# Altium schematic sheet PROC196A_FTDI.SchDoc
size 431 x 279 mm; Date: Not shown in title block; ApprovedBy: Not shown in title block; CheckedBy: Not shown in title block; Author: Not shown in title block; CompanyName: Not shown in title block; Engineer: Not shown in title block; Organization: Not shown in title block; Address1: Not shown in title block; Address2: Not shown in title block; Address3: Not shown in title block; Address4: Not shown in title block; DocumentNumber: 17; Revision: Use project parameter SCH_Rev; SheetNumber: 17; SheetTotal: 25; PageSetup: Record=PageOptions¦CenterHorizontal=True¦CenterVertical=True¦PrintScale=1.00¦XCorrection=1.00¦YCorrection=1.00¦PrintKind=0¦BorderSize=5000000¦LeftOffset=0¦BottomOffset=0¦Orientation=2¦PaperLength=1000¦PaperWidth=1000¦Scale=100¦PaperSource=15¦PrintQuality=600¦MediaType=1¦DitherType=10¦PaperKind=Letter¦PrintScaleMode=1
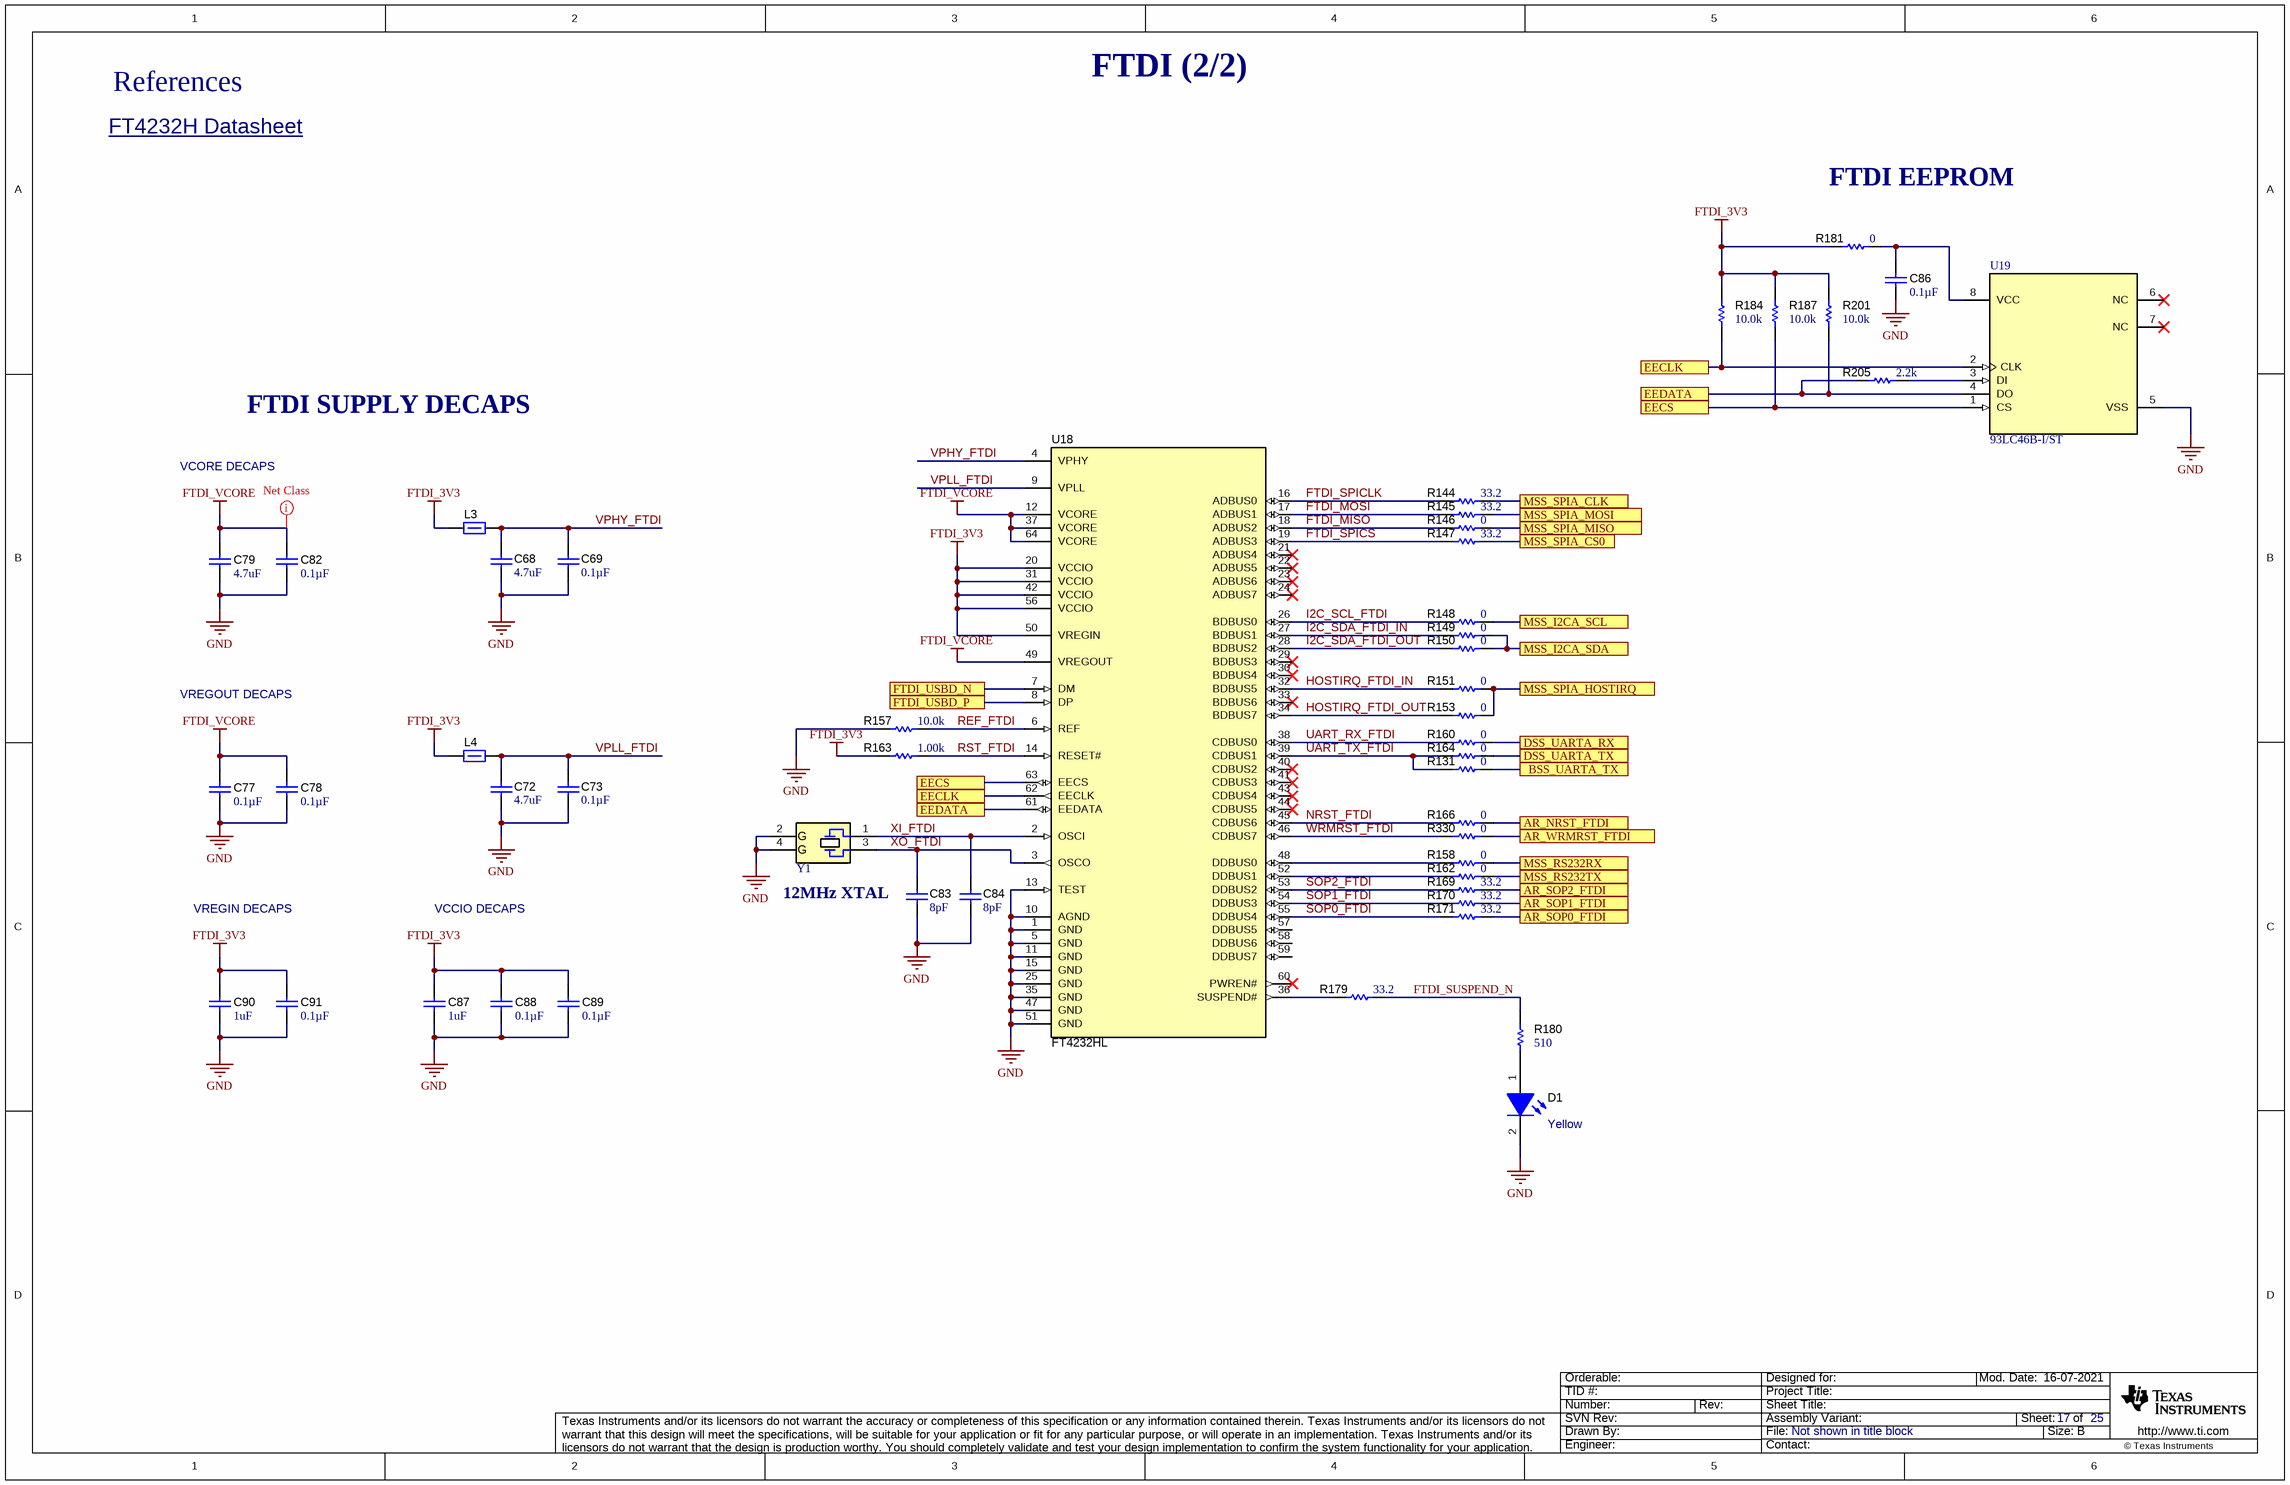
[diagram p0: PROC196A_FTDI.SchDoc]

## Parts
C68  ValueDisplayed: 4.7uF  [0603L]  (hidden comment: C1608X7S1A475K080AC)
C69  ValueDisplayed: 0.1µF  [0402L]  (hidden comment: C0402C104K8RACTU)
C72  ValueDisplayed: 4.7uF  [0603L]  (hidden comment: C1608X7S1A475K080AC)
C73  ValueDisplayed: 0.1µF  [0402L]  (hidden comment: C0402C104K8RACTU)
C77  ValueDisplayed: 0.1µF  [0402L]  (hidden comment: C0402C104K8RACTU)
C78  ValueDisplayed: 0.1µF  [0402L]  (hidden comment: C0402C104K8RACTU)
C79  ValueDisplayed: 4.7uF  [0603L]  (hidden comment: C1608X7S1A475K080AC)
C82  ValueDisplayed: 0.1µF  [0402L]  (hidden comment: C0402C104K8RACTU)
C83  Cap_F: 8pF  [0402L]  (hidden comment: GCM1555C1H8R0DA16D)
C84  Cap_F: 8pF  [0402L]  (hidden comment: GCM1555C1H8R0DA16D)
C86  ValueDisplayed: 0.1µF  [0402L]  (hidden comment: C0402C104K8RACTU)
C87  ValueDisplayed: 1uF  [0603L]  (hidden comment: GCM188R71C105KA64D)
C88  ValueDisplayed: 0.1µF  [0402L]  (hidden comment: C0402C104K8RACTU)
C89  ValueDisplayed: 0.1µF  [0402L]  (hidden comment: C0402C104K8RACTU)
C90  ValueDisplayed: 1uF  [0603L]  (hidden comment: GCM188R71C105KA64D)
C91  ValueDisplayed: 0.1µF  [0402L]  (hidden comment: C0402C104K8RACTU)
D1  value Yellow  [TLMx1000_Yellow]  (hidden comment: TLMY1000-GS08)
L3  BLM15HG601SN1D  [0402L]  (value not drawn)
L4  BLM15HG601SN1D  [0402L]  (value not drawn)
R131  ValueDisplayed: 0  [0402L]  (hidden comment: ERJ-2GE0R00X)
R144  ValueDisplayed: 33.2  [0402L]  (hidden comment: CRCW040233R2FKED)
R145  ValueDisplayed: 33.2  [0402L]  (hidden comment: CRCW040233R2FKED)
R146  ValueDisplayed: 0  [0402L]  (hidden comment: ERJ-2GE0R00X)
R147  ValueDisplayed: 33.2  [0402L]  (hidden comment: CRCW040233R2FKED)
R148  ValueDisplayed: 0  [0402L]  (hidden comment: ERJ-2GE0R00X)
R149  ValueDisplayed: 0  [0402L]  (hidden comment: ERJ-2GE0R00X)
R150  ValueDisplayed: 0  [0402L]  (hidden comment: ERJ-2GE0R00X)
R151  ValueDisplayed: 0  [0402L]  (hidden comment: ERJ-2GE0R00X)
R153  ValueDisplayed: 0  [0402L]  (hidden comment: ERJ-2GE0R00X)
R157  ValueDisplayed: 10.0k  [0402L]  (hidden comment: CRCW040210K0FKED)
R158  ValueDisplayed: 0  [0402L]  (hidden comment: ERJ-2GE0R00X)
R160  ValueDisplayed: 0  [0402L]  (hidden comment: ERJ-2GE0R00X)
R162  ValueDisplayed: 0  [0402L]  (hidden comment: ERJ-2GE0R00X)
R163  ValueDisplayed: 1.00k  [0402L]  (hidden comment: CRCW04021K00FKED)
R164  ValueDisplayed: 0  [0402L]  (hidden comment: ERJ-2GE0R00X)
R166  ValueDisplayed: 0  [0402L]  (hidden comment: ERJ-2GE0R00X)
R169  ValueDisplayed: 33.2  [0402L]  (hidden comment: CRCW040233R2FKED)
R170  ValueDisplayed: 33.2  [0402L]  (hidden comment: CRCW040233R2FKED)
R171  ValueDisplayed: 33.2  [0402L]  (hidden comment: CRCW040233R2FKED)
R179  ValueDisplayed: 33.2  [0402L]  (hidden comment: CRCW040233R2FKED)
R180  ValueDisplayed: 510  [0402L]  (hidden comment: ERJ-2GEJ511X)
R181  ValueDisplayed: 0  [0402L]  (hidden comment: ERJ-2GE0R00X)
R184  ValueDisplayed: 10.0k  [0402L]  (hidden comment: CRCW040210K0FKED)
R187  ValueDisplayed: 10.0k  [0402L]  (hidden comment: CRCW040210K0FKED)
R201  ValueDisplayed: 10.0k  [0402L]  (hidden comment: CRCW040210K0FKED)
R205  ValueDisplayed: 2.2k  [0402L]  (hidden comment: CRCW04022K20JNED)
R330  ValueDisplayed: 0  [0402L]  (hidden comment: ERJ-2GE0R00X)
U18  FT4232HL  [LQFP64_N]
U19  93LC46B-I/ST  [TSSOP-8]
Y1  NX3225SA-12.000M-STD-CRS-2  [NDK_NX3225SA]  (value not drawn)

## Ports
AR_NRST_FTDI, AR_SOP0_FTDI, AR_SOP1_FTDI, AR_SOP2_FTDI, AR_WRMRST_FTDI, BSS_UARTA_TX, DSS_UARTA_RX, DSS_UARTA_TX, EECLK, EECS, EEDATA, FTDI_USBD_N, FTDI_USBD_P, MSS_I2CA_SCL, MSS_I2CA_SDA, MSS_RS232RX, MSS_RS232TX, MSS_SPIA_CLK, MSS_SPIA_CS0, MSS_SPIA_HOSTIRQ, MSS_SPIA_MISO, MSS_SPIA_MOSI

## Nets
FTDI_3V3: C87.1 C88.1 C89.1 C90.1 C91.1 L3.1 L4.1 R163.1 R181.2 R184.2 R187.2 R201.2 U18.20(VCCIO) U18.31(VCCIO) U18.42(VCCIO) U18.50(VREGIN) U18.56(VCCIO)
FTDI_VCORE: C77.1 C78.1 C79.1 C82.1 U18.12(VCORE) U18.37(VCORE) U18.49(VREGOUT) U18.64(VCORE)
GND: C68.2 C69.1 C72.2 C73.1 C77.2 C78.2 C79.2 C82.2 C83.2 C84.2 C86.2 C87.2 C88.2 C89.2 C90.2 C91.2 D1.2(K) R157.1 U18.1(GND) U18.5(GND) U18.10(AGND) U18.11(GND) U18.13(TEST) U18.15(GND) U18.25(GND) U18.35(GND) U18.47(GND) U18.51(GND) U19.5(VSS) Y1.2(GND) Y1.4(GND)
AR_NRST_FTDI: R166.2 ; port AR_NRST_FTDI
AR_SOP0_FTDI: R171.2 ; port AR_SOP0_FTDI
AR_SOP1_FTDI: R170.2 ; port AR_SOP1_FTDI
AR_SOP2_FTDI: R169.2 ; port AR_SOP2_FTDI
AR_WRMRST_FTDI: R330.2 ; port AR_WRMRST_FTDI
BSS_UARTA_TX: R131.1 ; port BSS_UARTA_TX
DSS_UARTA_RX: R160.2 ; port DSS_UARTA_RX
DSS_UARTA_TX: R164.2 ; port DSS_UARTA_TX
EECLK: R184.1 U18.62(EECLK) U19.2(CLK) ; port EECLK
EECS: R187.1 U18.63(EECS) U19.1(CS) ; port EECS
EEDATA: R201.1 R205.1 U18.61(EEDATA) U19.4(DO) ; port EEDATA
FTDI_MISO: R146.1 U18.18(ADBUS2)
FTDI_MOSI: R145.1 U18.17(ADBUS1)
FTDI_SPICLK: R144.1 U18.16(ADBUS0)
FTDI_SPICS: R147.1 U18.19(ADBUS3)
FTDI_SUSPEND_N: R179.2 R180.2
FTDI_USBD_N: U18.7(DM) ; port FTDI_USBD_N
FTDI_USBD_P: U18.8(DP) ; port FTDI_USBD_P
HOSTIRQ_FTDI_IN: R151.1 U18.32(BDBUS5)
HOSTIRQ_FTDI_OUT: R153.1 U18.34(BDBUS7)
I2C_SCL_FTDI: R148.1 U18.26(BDBUS0)
I2C_SDA_FTDI_IN: R149.1 U18.27(BDBUS1)
I2C_SDA_FTDI_OUT: R150.1 U18.28(BDBUS2)
MSS_I2CA_SCL: R148.2 ; port MSS_I2CA_SCL
MSS_I2CA_SDA: R149.2 R150.2 ; port MSS_I2CA_SDA
MSS_RS232RX: R158.2 ; port MSS_RS232RX
MSS_RS232TX: R162.2 ; port MSS_RS232TX
MSS_SPIA_CLK: R144.2 ; port MSS_SPIA_CLK
MSS_SPIA_CS0: R147.2 ; port MSS_SPIA_CS0
MSS_SPIA_HOSTIRQ: R151.2 R153.2 ; port MSS_SPIA_HOSTIRQ
MSS_SPIA_MISO: R146.2 ; port MSS_SPIA_MISO
MSS_SPIA_MOSI: R145.2 ; port MSS_SPIA_MOSI
NRST_FTDI: R166.1 U18.45(CDBUS6)
REF_FTDI: R157.2 U18.6(REF)
RST_FTDI: R163.2 U18.14(RESET#)
SOP0_FTDI: R171.1 U18.55(DDBUS4)
SOP1_FTDI: R170.1 U18.54(DDBUS3)
SOP2_FTDI: R169.1 U18.53(DDBUS2)
UART_RX_FTDI: R160.1 U18.38(CDBUS0)
UART_TX_FTDI: R131.2 R164.1 U18.39(CDBUS1)
VPHY_FTDI: C68.1 C69.2 L3.2 U18.4(VPHY)
VPLL_FTDI: C72.1 C73.2 L4.2 U18.9(VPLL)
WRMRST_FTDI: R330.1 U18.46(CDBUS7)
XI_FTDI: C84.1 U18.2(OSCI) Y1.1
XO_FTDI: C83.1 U18.3(OSCO) Y1.3
NetC86_1: C86.1 R181.1 U19.8(VCC)
NetD1_1: D1.1(A) R180.1
NetR158_1: R158.1 U18.48(DDBUS0)
NetR162_1: R162.1 U18.52(DDBUS1)
NetR179_1: R179.1 U18.36(SUSPEND#)
NetR205_2: R205.2 U19.3(DI)

Not connected (* = marked no-connect by the designer): U18 21(ADBUS4)* 22(ADBUS5)* 23(ADBUS6)* 24(ADBUS7)* 29(BDBUS3)* 30(BDBUS4)* 33(BDBUS6)* 40(CDBUS2)* 41(CDBUS3)* 43(CDBUS4)* 44(CDBUS5)* 57(DDBUS5) 58(DDBUS6) 59(DDBUS7) 60(PWREN#)*; U19 6(NC)* 7(NC)*

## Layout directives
net class PWR: FTDI_VCORE

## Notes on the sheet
- References
- FTDI (2/2)
- FT4232H Datasheet <https://www.ftdichip.com/Support/Documents/DataSheets/ICs/DS_FT4232H.pdf>
- FTDI EEPROM
- FTDI SUPPLY DECAPS
- VCORE DECAPS
- VREGOUT DECAPS
- 12MHz XTAL
- VREGIN DECAPS
- VCCIO DECAPS

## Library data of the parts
C68 C72 C79 = CMP-0007058-4: CAP, CERM, 4.7 uF, 10 V, +/- 10%, X7S, 0603; Manufacturer: TDK; TaMin_C: -55°C; Polarized: N; SizeAreaWB_mm2: 4.68; Value1: Unknown; U/M: EA; Value: 4.7uF; TaMax_C: 125°C; SizeZ_mm: 1; SizeX_mm: 1.6; SizeY_mm: 0.8; Cap_Case: 0603; Value2: 10V; SizeArea_mm2: 1.28; CompType: Capacitor; Cap_F: 4.7µF; AEC Category: Q200
C69 C73 C77 C78 C82 C86 C88 C89 C91 = CMP-0078241-1: CAP, CERM, 0.1 µF, 10 V,+/- 10%, X7R, 0402; Manufacturer: Kemet; TaMin_C: -55°C; Polarized: N; SizeAreaWB_mm2: 3; U/M: EA; Value: 0.1uF; TaMax_C: 125°C; SizeZ_mm: 0.6; SizeX_mm: 1; SizeY_mm: 0.5; Cap_Case: 0402; Value2: 10V; CompType: Capacitor; Cap_F: 100nF; AEC Category: Q200
C83 C84 = CMP-0087060-3: Cap Ceramic 8pF 50V C0G 0.5pF SMD 0402 125C Paper T/R; Manufacturer: Murata Electronics North America; AEC Qualified: Yes; TempCo: 30ppm/°C; AEC Grade: Grade 1; SizeZ_mm: 0.55mm
C87 C90 = CMP-0007136-5: CAP, CERM, 1 uF, 16 V, +/- 10%, X7R, AEC-Q200 Grade 1, 0603; Manufacturer: MuRata; TaMin_C: -55°C; Polarized: N; SizeAreaWB_mm2: 4.68; Value1: Unknown; U/M: EA; Value: 1uF; TaMax_C: 125°C; SizeZ_mm: 1; SizeX_mm: 1.6; SizeY_mm: 0.8; Cap_Case: 0603; Value2: 16V; SizeArea_mm2: 1.28; CompType: Capacitor; AEC Qualified: Y; Cap_F: 1µF; AEC Category: Q200
D1 = CMP-0078196-2: LED, Yellow, SMD; Manufacturer: Vishay-Semiconductor; Tjmax_C: 120°C; SizeAreaWB_mm2: 4.68; Vr_V: 6V; Power_TotalModule: 40mW; Angle: 160; SizeArea_mm2: 1.28; Ir_A: 10µA; SizeZ_mm: 0.65; Io_A: 2mA; Vf_V: 1.8V; SizeY_mm: 0.8; Value1: .04W; SizeX_mm: 1.6; Type: AlInGaP
L3 L4 = CMP-0081523-1: Ferrite Bead, 600 ohm @ 100 MHz, 0.3 A, 0402; Manufacturer: MuRata; SizeAreaWB_mm2: 3; SizeArea_mm2: 0.5; Value: 600 ohm; SizeZ_mm: 0.6; Imax_A: 3dA; ZTyp@100MHz_Ohm: 600; Value2: 0.3A; Value1: 0.7 ohm; DCR_ohm: 7d; SizeX_mm: 1; Ztyp@1GHz_Ohm: 1k
R131 R158 R160 R162 R164 = CMP-0026992-3: RES, 0, 5%, 0.1 W, AEC-Q200 Grade 0, 0402; Manufacturer: Panasonic; Power_W: 100mW; TempCo: 600 ppm/C; Value_Code: 0000; Value: 0; EIA_Code: E24; SizeX_mm: 1; SizeY_mm: 0.5; SizeZ_mm: 0.6; Value2: 0.1W; CompType: Resistor; AEC Qualified: Y; VDC_V: 50V; AEC Category: Q200; SizeAreaWB_mm2: 3; INSTALLATION: DNP
R144 R145 R147 R169-R171 R179 = CMP-0026299-2: RES, 33.2, 1%, 0.063 W, AEC-Q200 Grade 0, 0402; Manufacturer: Vishay-Dale; Power_W: 63mW; TempCo: 100 ppm/C; Value_Code: 33R2; Value: 33.2; EIA_Code: E96; SizeX_mm: 1; SizeY_mm: 0.5; SizeZ_mm: 0.6; Value2: 0.063W; AEC Qualified: Y; VDC_V: 50V; AEC Category: Q200; AEC Grade: 0
R146 R148-R151 R153 R166 R181 R330 = CMP-0026992-3: RES, 0, 5%, 0.1 W, AEC-Q200 Grade 0, 0402; Manufacturer: Panasonic; Power_W: 100mW; TempCo: 600 ppm/C; Value_Code: 0000; Value: 0; EIA_Code: E24; SizeX_mm: 1; SizeY_mm: 0.5; SizeZ_mm: 0.6; Value2: 0.1W; AEC Qualified: Y; VDC_V: 50V; AEC Category: Q200; SizeAreaWB_mm2: 3
R157 R184 R187 R201 = CMP-0025958-3: RES, 10.0 k, 1%, 0.063 W, AEC-Q200 Grade 0, 0402; Manufacturer: Vishay-Dale; Power_W: 63mW; TempCo: 100 ppm/C; Value_Code: 10k0; Value: 10.0k; EIA_Code: E96; Res_ohm: 10k; SizeX_mm: 1; SizeY_mm: 0.5; SizeZ_mm: 0.6; Value2: 0.063W; AEC Qualified: Y; VDC_V: 50V; AEC Category: Q200; AEC Grade: 0
R163 = CMP-0026071-3: RES, 1.00 k, 1%, 0.063 W, AEC-Q200 Grade 0, 0402; Manufacturer: Vishay-Dale; Power_W: 63mW; TempCo: 100 ppm/C; Value_Code: 1k00; Value: 1.00k; EIA_Code: E96; Res_ohm: 1k; SizeX_mm: 1; SizeY_mm: 0.5; SizeZ_mm: 0.6; Value2: 0.063W; AEC Qualified: Y; VDC_V: 50V; AEC Category: Q200; AEC Grade: 0
R180 = CMP-0078212-1: RES, 510, 5%, 0.1 W, AEC-Q200 Grade 0, 0402; Manufacturer: Panasonic; Value_Code: 510R; SizeArea_mm2: 0.5; AEC Qualified: Y; AEC Category: Q200; Value: 510; SizeZ_mm: 0.6; EIA_Code: E24; TempCo: 200 ppm/C; AEC Grade: 0; Power_W: 100mW; VDC_V: 50V; Value2: 0.1W; U/M: EA; SizeX_mm: 1
R205 = CMP-0026890-5: RES, 2.2 k, 5%, 0.063 W, AEC-Q200 Grade 0, 0402; Manufacturer: Vishay-Dale; Power_W: 63mW; TempCo: 200 ppm/C; Value_Code: 2k20; Value: 2.2k; EIA_Code: E24; SizeX_mm: 1; SizeY_mm: 0.5; SizeZ_mm: 0.6; Value2: 0.063W; AEC Qualified: Y; VDC_V: 50V; AEC Category: Q200; AEC Grade: 0
U18 = CMP-0004747-1: Quad High Speed USB to Multipurpose UART/MPSSE IC; Manufacturer: FTDI
U19 = CMP-0081524-1: 1K Microwire Compatible Serial EEPROM, TSSOP-8; Manufacturer: Microchip; SizeArea_mm2: 19.2; SizeAreaWB_mm2: 42; SizeY_mm: 3; SizeZ_mm: 1.2; SizeX_mm: 6.4
Y1 = CMP-0081529-1: Crystal, 12 MHz, 15 ppm, 8 pF, AEC-Q200 Grade 1, SMD; Manufacturer: NDK; TaMin_C: -40°C; Frequency Tolerance: 15 ppm; Frequency Stability: 50 ppm; Load Capacitance: 8 pF; Frequency_Fixed: 12MHz; TaMax_C: 125°C; AEC Qualified: Y; AEC Grade: 1; AEC Category: Q200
